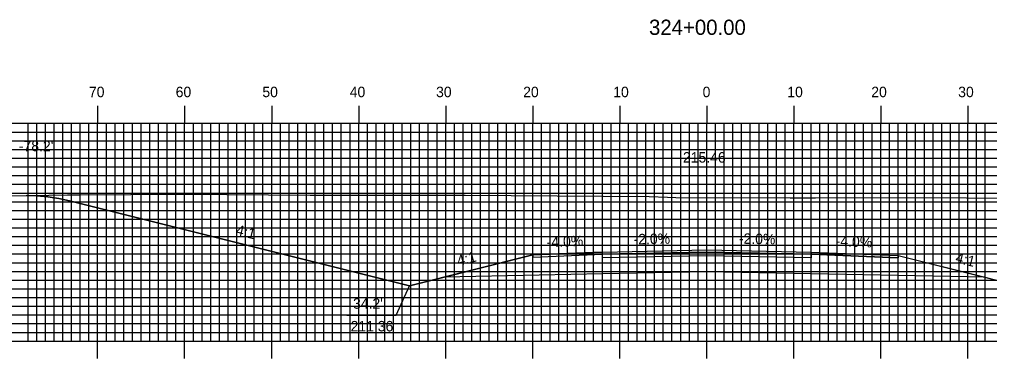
# Model space of a CAD drawing. Extents: x 1820818 to 1821161, y 442591 to 442811.
# Drawn here: x 1820904.7 to 1821016.2, y 442696.7 to 442735.6 of the extents above; entities that cross this region are included whole.
import ezdxf

# ---------------------------------------------------------------- set-up
doc = ezdxf.new("R2010")
doc.units = 0
for name, color, linetype in [('ANNOTATION', 7, 'Continuous'), ('D_Roadway_Centerline', 7, 'Continuous'), ('D_Roadway_Centerline_Text', 7, 'Continuous'), ('D_Roadway_Edge_Shoulder', 7, 'Continuous'), ('D_Roadway_Edge_TW', 7, 'Continuous'), ('D_Roadway_Pavement', 7, 'Continuous'), ('D_Roadway_SlopeLines', 7, 'Continuous'), ('D_Roadway_SubGrade', 7, 'Continuous'), ('D_Text_Standard', 7, 'Continuous'), ('H_V ANNOTATION', 7, 'Continuous'), ('MAJOR', 7, 'Continuous'), ('MINOR', 7, 'Continuous'), ('S_Roadway_Centerline', 7, 'Continuous')]:
    doc.layers.add(name, color=color, linetype=linetype)

msp = doc.modelspace()

# ---------------------------------------------------------------- linework, layer by layer
at = {"layer": 'ANNOTATION'}
msp.add_lwpolyline([(1820942.34, 442701.65), (1820948.03, 442701.65), (1820949.54, 442705.02)], dxfattribs=at)
at = {"layer": 'D_Roadway_Centerline'}
msp.add_lwpolyline([(1820905.5, 442715.37), (1820906.75, 442715.35), (1820908, 442715.24), (1820909.25, 442715.05), (1820910.5, 442714.78), (1820949.54, 442705.02), (1820953.54, 442706.02), (1820963.72, 442708.57), (1820971.72, 442708.89), (1820983.72, 442709.13), (1820995.72, 442708.89), (1821005.72, 442708.49), (1821015.72, 442705.99), (1821019.72, 442704.99), (1821054.78, 442713.75), (1821056.03, 442714.02), (1821057.28, 442714.22), (1821058.53, 442714.33), (1821059.78, 442714.37)], dxfattribs=at)
at = {"layer": 'D_Roadway_Edge_Shoulder'}
for points in [[(1820971.72, 442708.89), (1820963.72, 442708.57), (1820963.72, 442708.32), (1820971.72, 442708.64)], [(1820995.72, 442708.89), (1821005.72, 442708.49), (1821005.72, 442708.24), (1820995.72, 442708.64)]]:
    msp.add_lwpolyline(points, close=True, dxfattribs=at)
at = {"layer": 'D_Roadway_Edge_TW'}
msp.add_lwpolyline([(1820971.72, 442708.64), (1820971.72, 442708.89), (1820983.72, 442709.13), (1820995.72, 442708.89), (1820995.72, 442708.64), (1820983.72, 442708.88)], close=True, dxfattribs=at)
at = {"layer": 'D_Roadway_Pavement'}
msp.add_lwpolyline([(1820971.72, 442708.22), (1820971.72, 442708.64), (1820983.72, 442708.88), (1820995.72, 442708.64), (1820995.72, 442708.22), (1820983.72, 442708.46)], close=True, dxfattribs=at)
at = {"layer": 'D_Roadway_SlopeLines'}
for points in [[(1820949.54, 442705.02), (1820910.5, 442714.78), (1820909.25, 442715.05), (1820908, 442715.24), (1820906.75, 442715.35), (1820905.5, 442715.37)], [(1820963.72, 442708.57), (1820949.54, 442705.02)], [(1821005.72, 442708.49), (1821019.72, 442704.99)]]:
    msp.add_lwpolyline(points, dxfattribs=at)
at = {"layer": 'D_Roadway_SubGrade'}
msp.add_lwpolyline([(1820971.72, 442706.39), (1820953.54, 442706.02), (1820963.72, 442708.57), (1820963.72, 442708.32), (1820971.72, 442708.64), (1820983.72, 442708.88), (1820995.72, 442708.64), (1821005.72, 442708.24), (1821005.72, 442708.49), (1821015.72, 442705.99), (1820995.72, 442706.39), (1820983.72, 442706.63)], close=True, dxfattribs=at)
at = {"layer": 'MAJOR'}
for p, q in [((1820913.72, 442725.67), (1820913.72, 442723.67)), ((1820923.72, 442725.67), (1820923.72, 442723.67)), ((1820933.72, 442725.67), (1820933.72, 442723.67)), ((1820943.72, 442725.67), (1820943.72, 442723.67)), ((1820953.72, 442725.67), (1820953.72, 442723.67)), ((1820963.72, 442725.67), (1820963.72, 442723.67)), ((1820973.72, 442725.67), (1820973.72, 442723.67)), ((1820983.72, 442725.67), (1820983.72, 442723.67)), ((1820993.72, 442725.67), (1820993.72, 442723.67)), ((1821003.72, 442725.67), (1821003.72, 442723.67)), ((1821013.72, 442725.67), (1821013.72, 442723.67)), ((1820843.72, 442723.67), (1821123.72, 442723.67)), ((1820843.72, 442723.67), (1821123.72, 442723.67)), ((1820913.72, 442698.67), (1820913.72, 442723.67)), ((1820923.72, 442698.67), (1820923.72, 442723.67)), ((1820933.72, 442698.67), (1820933.72, 442723.67)), ((1820943.72, 442698.67), (1820943.72, 442723.67)), ((1820953.72, 442698.67), (1820953.72, 442723.67)), ((1820963.72, 442698.67), (1820963.72, 442723.67)), ((1820973.72, 442698.67), (1820973.72, 442723.67)), ((1820983.72, 442698.67), (1820983.72, 442723.67)), ((1820993.72, 442698.67), (1820993.72, 442723.67)), ((1821003.72, 442698.67), (1821003.72, 442723.67)), ((1821013.72, 442698.67), (1821013.72, 442723.67)), ((1820843.72, 442718.67), (1821123.72, 442718.67)), ((1820843.72, 442713.67), (1821123.72, 442713.67)), ((1820843.72, 442708.67), (1821123.72, 442708.67)), ((1820843.72, 442703.67), (1821123.72, 442703.67)), ((1820843.72, 442698.67), (1821123.72, 442698.67)), ((1820843.72, 442698.67), (1821123.72, 442698.67)), ((1820913.72, 442696.66), (1820913.72, 442698.67)), ((1820923.72, 442696.66), (1820923.72, 442698.67)), ((1820933.72, 442696.66), (1820933.72, 442698.67)), ((1820943.72, 442696.66), (1820943.72, 442698.67)), ((1820953.72, 442696.66), (1820953.72, 442698.67)), ((1820963.72, 442696.66), (1820963.72, 442698.67)), ((1820973.72, 442696.66), (1820973.72, 442698.67)), ((1820983.72, 442696.66), (1820983.72, 442698.67)), ((1820993.72, 442696.66), (1820993.72, 442698.67)), ((1821003.72, 442696.66), (1821003.72, 442698.67)), ((1821013.72, 442696.66), (1821013.72, 442698.67))]:
    msp.add_line(p, q, dxfattribs=at)
at = {"layer": 'MINOR'}
for p, q in [((1820843.72, 442722.67), (1821123.72, 442722.67)), ((1820905.72, 442698.67), (1820905.72, 442723.67)), ((1820906.72, 442698.67), (1820906.72, 442723.67)), ((1820907.72, 442698.67), (1820907.72, 442723.67)), ((1820908.72, 442698.67), (1820908.72, 442723.67)), ((1820909.72, 442698.67), (1820909.72, 442723.67)), ((1820910.72, 442698.67), (1820910.72, 442723.67)), ((1820911.72, 442698.67), (1820911.72, 442723.67)), ((1820912.72, 442698.67), (1820912.72, 442723.67)), ((1820914.72, 442698.67), (1820914.72, 442723.67)), ((1820915.72, 442698.67), (1820915.72, 442723.67)), ((1820916.72, 442698.67), (1820916.72, 442723.67)), ((1820917.72, 442698.67), (1820917.72, 442723.67)), ((1820918.72, 442698.67), (1820918.72, 442723.67)), ((1820919.72, 442698.67), (1820919.72, 442723.67)), ((1820920.72, 442698.67), (1820920.72, 442723.67)), ((1820921.72, 442698.67), (1820921.72, 442723.67)), ((1820922.72, 442698.67), (1820922.72, 442723.67)), ((1820924.72, 442698.67), (1820924.72, 442723.67)), ((1820925.72, 442698.67), (1820925.72, 442723.67)), ((1820926.72, 442698.67), (1820926.72, 442723.67)), ((1820927.72, 442698.67), (1820927.72, 442723.67)), ((1820928.72, 442698.67), (1820928.72, 442723.67)), ((1820929.72, 442698.67), (1820929.72, 442723.67)), ((1820930.72, 442698.67), (1820930.72, 442723.67)), ((1820931.72, 442698.67), (1820931.72, 442723.67)), ((1820932.72, 442698.67), (1820932.72, 442723.67)), ((1820934.72, 442698.67), (1820934.72, 442723.67)), ((1820935.72, 442698.67), (1820935.72, 442723.67)), ((1820936.72, 442698.67), (1820936.72, 442723.67)), ((1820937.72, 442698.67), (1820937.72, 442723.67)), ((1820938.72, 442698.67), (1820938.72, 442723.67)), ((1820939.72, 442698.67), (1820939.72, 442723.67)), ((1820940.72, 442698.67), (1820940.72, 442723.67)), ((1820941.72, 442698.67), (1820941.72, 442723.67)), ((1820942.72, 442698.67), (1820942.72, 442723.67)), ((1820944.72, 442698.67), (1820944.72, 442723.67)), ((1820945.72, 442698.67), (1820945.72, 442723.67)), ((1820946.72, 442698.67), (1820946.72, 442723.67)), ((1820947.72, 442698.67), (1820947.72, 442723.67)), ((1820948.72, 442698.67), (1820948.72, 442723.67)), ((1820949.72, 442698.67), (1820949.72, 442723.67)), ((1820950.72, 442698.67), (1820950.72, 442723.67)), ((1820951.72, 442698.67), (1820951.72, 442723.67)), ((1820952.72, 442698.67), (1820952.72, 442723.67)), ((1820954.72, 442698.67), (1820954.72, 442723.67)), ((1820955.72, 442698.67), (1820955.72, 442723.67)), ((1820956.72, 442698.67), (1820956.72, 442723.67)), ((1820957.72, 442698.67), (1820957.72, 442723.67)), ((1820958.72, 442698.67), (1820958.72, 442723.67)), ((1820959.72, 442698.67), (1820959.72, 442723.67)), ((1820960.72, 442698.67), (1820960.72, 442723.67)), ((1820961.72, 442698.67), (1820961.72, 442723.67)), ((1820962.72, 442698.67), (1820962.72, 442723.67)), ((1820964.72, 442698.67), (1820964.72, 442723.67)), ((1820965.72, 442698.67), (1820965.72, 442723.67)), ((1820966.72, 442698.67), (1820966.72, 442723.67)), ((1820967.72, 442698.67), (1820967.72, 442723.67)), ((1820968.72, 442698.67), (1820968.72, 442723.67)), ((1820969.72, 442698.67), (1820969.72, 442723.67)), ((1820970.72, 442698.67), (1820970.72, 442723.67)), ((1820971.72, 442698.67), (1820971.72, 442723.67)), ((1820972.72, 442698.67), (1820972.72, 442723.67)), ((1820974.72, 442698.67), (1820974.72, 442723.67)), ((1820975.72, 442698.67), (1820975.72, 442723.67)), ((1820976.72, 442698.67), (1820976.72, 442723.67)), ((1820977.72, 442698.67), (1820977.72, 442723.67)), ((1820978.72, 442698.67), (1820978.72, 442723.67)), ((1820979.72, 442698.67), (1820979.72, 442723.67)), ((1820980.72, 442698.67), (1820980.72, 442723.67)), ((1820981.72, 442698.67), (1820981.72, 442723.67)), ((1820982.72, 442698.67), (1820982.72, 442723.67)), ((1820984.72, 442698.67), (1820984.72, 442723.67)), ((1820985.72, 442698.67), (1820985.72, 442723.67)), ((1820986.72, 442698.67), (1820986.72, 442723.67)), ((1820987.72, 442698.67), (1820987.72, 442723.67)), ((1820988.72, 442698.67), (1820988.72, 442723.67)), ((1820989.72, 442698.67), (1820989.72, 442723.67)), ((1820990.72, 442698.67), (1820990.72, 442723.67)), ((1820991.72, 442698.67), (1820991.72, 442723.67)), ((1820992.72, 442698.67), (1820992.72, 442723.67)), ((1820994.72, 442698.67), (1820994.72, 442723.67)), ((1820995.72, 442698.67), (1820995.72, 442723.67)), ((1820996.72, 442698.67), (1820996.72, 442723.67)), ((1820997.72, 442698.67), (1820997.72, 442723.67)), ((1820998.72, 442698.67), (1820998.72, 442723.67)), ((1820999.72, 442698.67), (1820999.72, 442723.67)), ((1821000.72, 442698.67), (1821000.72, 442723.67)), ((1821001.72, 442698.67), (1821001.72, 442723.67)), ((1821002.72, 442698.67), (1821002.72, 442723.67)), ((1821004.72, 442698.67), (1821004.72, 442723.67)), ((1821005.72, 442698.67), (1821005.72, 442723.67)), ((1821006.72, 442698.67), (1821006.72, 442723.67)), ((1821007.72, 442698.67), (1821007.72, 442723.67)), ((1821008.72, 442698.67), (1821008.72, 442723.67)), ((1821009.72, 442698.67), (1821009.72, 442723.67)), ((1821010.72, 442698.67), (1821010.72, 442723.67)), ((1821011.72, 442698.67), (1821011.72, 442723.67)), ((1821012.72, 442698.67), (1821012.72, 442723.67)), ((1821014.72, 442698.67), (1821014.72, 442723.67)), ((1821015.72, 442698.67), (1821015.72, 442723.67)), ((1820843.72, 442721.67), (1821123.72, 442721.67)), ((1820843.72, 442720.67), (1821123.72, 442720.67)), ((1820843.72, 442719.67), (1821123.72, 442719.67)), ((1820843.72, 442717.67), (1821123.72, 442717.67)), ((1820843.72, 442716.67), (1821123.72, 442716.67)), ((1820843.72, 442715.67), (1821123.72, 442715.67)), ((1820843.72, 442714.67), (1821123.72, 442714.67)), ((1820843.72, 442712.67), (1821123.72, 442712.67)), ((1820843.72, 442711.67), (1821123.72, 442711.67)), ((1820843.72, 442710.67), (1821123.72, 442710.67)), ((1820843.72, 442709.67), (1821123.72, 442709.67)), ((1820843.72, 442707.67), (1821123.72, 442707.67)), ((1820843.72, 442706.67), (1821123.72, 442706.67)), ((1820843.72, 442705.67), (1821123.72, 442705.67)), ((1820843.72, 442704.67), (1821123.72, 442704.67)), ((1820843.72, 442702.67), (1821123.72, 442702.67)), ((1820843.72, 442701.67), (1821123.72, 442701.67)), ((1820843.72, 442700.67), (1821123.72, 442700.67)), ((1820843.72, 442699.67), (1821123.72, 442699.67))]:
    msp.add_line(p, q, dxfattribs=at)
at = {"layer": 'S_Roadway_Centerline'}
msp.add_lwpolyline([(1820843.72, 442716.12), (1820854.99, 442715.91), (1820859.22, 442715.84), (1820861.5, 442715.82), (1820874.2, 442715.6), (1820883.79, 442715.59), (1820895.28, 442715.19), (1820910.24, 442715.45), (1820911.6, 442715.46), (1820923.49, 442715.52), (1820928.55, 442715.48), (1820938.15, 442715.42), (1820945.92, 442715.43), (1820955.97, 442715.42), (1820977.1, 442715.26), (1820979.21, 442715.19), (1820980.17, 442715.17), (1820993.31, 442715.11), (1820996.2, 442715.11), (1821004.69, 442715.17), (1821013.58, 442715.11), (1821018.78, 442715.08)], dxfattribs=at)

# ---------------------------------------------------------------- texts
at = {"layer": 'ANNOTATION'}
for s, rotation, p in [('4:1', 345.9638, (1820929.53, 442710.89)), ('-4.0%', 2.2906, (1820965.35, 442709.43)), ('-2.0%', 1.1458, (1820975.32, 442709.76)), ('-2.0%', 358.8542, (1820987.4, 442709.85)), ('-4.0%', 357.7094, (1820998.51, 442709.58)), ('4:1', 14.0362, (1820955.17, 442707.29)), ('4:1', 345.9638, (1821012.22, 442707.72))]:
    msp.add_text(s, height=1.2, rotation=rotation, dxfattribs=at).set_placement(p)
for s, p in [("34.2'", (1820943.07, 442702.38)), ('211.36', (1820942.79, 442699.78))]:
    msp.add_text(s, height=1.2, dxfattribs=at).set_placement(p)
at = {"layer": 'D_Roadway_Centerline'}
for s, p in [('C', (1820983.71, 442709.13)), ('L', (1820983.72, 442709.12))]:
    msp.add_text(s, height=0.0146, dxfattribs=at).set_placement(p)
at = {"layer": 'D_Roadway_Centerline_Text'}
msp.add_text('215.46', height=1.2, dxfattribs=at).set_placement((1820980.98, 442719.16))
at = {"layer": 'D_Text_Standard'}
msp.add_text("-78.2'", height=1.2, dxfattribs=at).set_placement((1820904.67, 442720.47))
at = {"layer": 'H_V ANNOTATION'}
for s, height, p in [('324+00.00', 1.75, (1820977.08, 442733.82)), ('70', 1.2, (1820912.72, 442726.67)), ('60', 1.2, (1820922.69, 442726.67)), ('50', 1.2, (1820932.65, 442726.67)), ('40', 1.2, (1820942.69, 442726.67)), ('30', 1.2, (1820952.61, 442726.67)), ('20', 1.2, (1820962.62, 442726.67)), ('10', 1.2, (1820972.97, 442726.67)), ('0', 1.2, (1820983.24, 442726.67)), ('10', 1.2, (1820992.97, 442726.67)), ('20', 1.2, (1821002.62, 442726.67)), ('30', 1.2, (1821012.61, 442726.67))]:
    msp.add_text(s, height=height, dxfattribs=at).set_placement(p)

doc.saveas('drawing.dxf')
